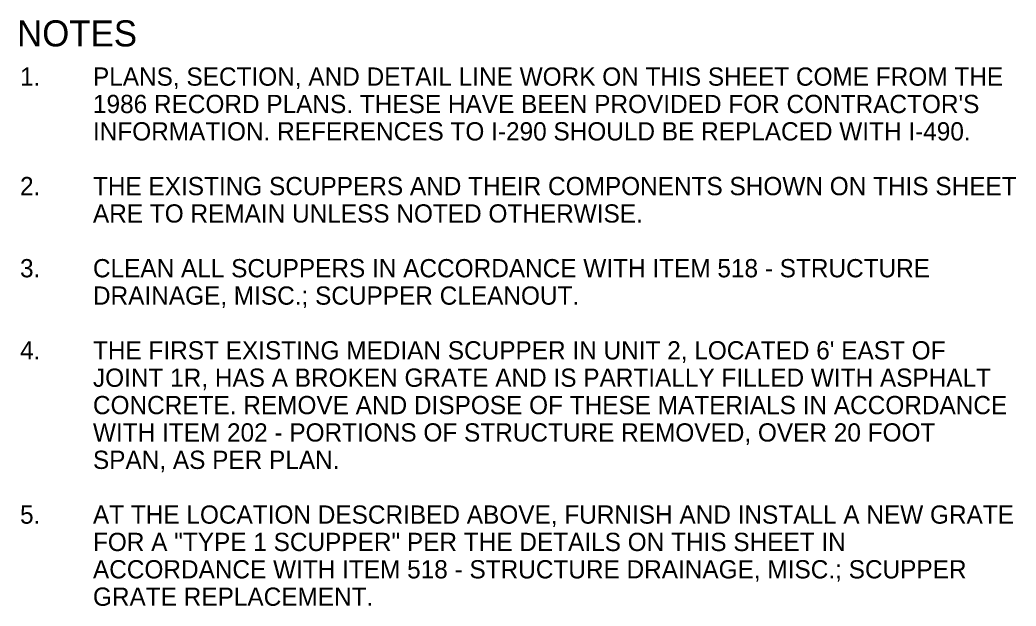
# Model space of a CAD drawing. Extents: x 2.6 to 34.2, y 0.7 to 15.7.
# Drawn here: x 2.6 to 10.25, y 0.67 to 5.17 of the extents above; entities that cross this region are included whole.
import ezdxf

# ---------------------------------------------------------------- set-up
doc = ezdxf.new("R2010")
doc.units = 0
doc.layers.add('SC_Scratch1', color=7, linetype='Continuous')

msp = doc.modelspace()

# ---------------------------------------------------------------- texts
at = {"layer": 'SC_Scratch1'}
for s, height, p in [('NOTES', 0.2, (2.5819, 4.9643)), ('1.', 0.14, (2.6047, 4.6627)), ('PLANS, SECTION, AND DETAIL LINE WORK ON THIS SHEET COME FROM THE ', 0.14, (3.1647, 4.6627)), ("1986 RECORD PLANS. THESE HAVE BEEN PROVIDED FOR CONTRACTOR'S ", 0.14, (3.1647, 4.4527)), ('INFORMATION. REFERENCES TO I-290 SHOULD BE REPLACED WITH I-490.', 0.14, (3.1647, 4.2427)), ('2.', 0.14, (2.6047, 3.8227)), ('THE EXISTING SCUPPERS AND THEIR COMPONENTS SHOWN ON THIS SHEET ', 0.14, (3.1647, 3.8227)), ('ARE TO REMAIN UNLESS NOTED OTHERWISE.', 0.14, (3.1647, 3.6127)), ('3.', 0.14, (2.6047, 3.1927)), ('CLEAN ALL SCUPPERS IN ACCORDANCE WITH ITEM 518 - STRUCTURE ', 0.14, (3.1647, 3.1927)), ('DRAINAGE, MISC.; SCUPPER CLEANOUT.', 0.14, (3.1647, 2.9827)), ('4.', 0.14, (2.6047, 2.5627)), ("THE FIRST EXISTING MEDIAN SCUPPER IN UNIT 2, LOCATED 6' EAST OF ", 0.14, (3.1647, 2.5627)), ('JOINT 1R, HAS A BROKEN GRATE AND IS PARTIALLY FILLED WITH ASPHALT ', 0.14, (3.1647, 2.3527)), ('CONCRETE. REMOVE AND DISPOSE OF THESE MATERIALS IN ACCORDANCE ', 0.14, (3.1647, 2.1427)), ('WITH ITEM 202 - PORTIONS OF STRUCTURE REMOVED, OVER 20 FOOT ', 0.14, (3.1647, 1.9327)), ('SPAN, AS PER PLAN.', 0.14, (3.1647, 1.7227)), ('5.', 0.14, (2.6047, 1.3027)), ('AT THE LOCATION DESCRIBED ABOVE, FURNISH AND INSTALL A NEW GRATE ', 0.14, (3.1647, 1.3027)), ('FOR A "TYPE 1 SCUPPER" PER THE DETAILS ON THIS SHEET IN ', 0.14, (3.1647, 1.0927)), ('ACCORDANCE WITH ITEM 518 - STRUCTURE DRAINAGE, MISC.; SCUPPER ', 0.14, (3.1647, 0.8827)), ('GRATE REPLACEMENT.', 0.14, (3.1647, 0.6727))]:
    msp.add_text(s, height=height, dxfattribs=at).set_placement(p)

doc.saveas('drawing.dxf')
